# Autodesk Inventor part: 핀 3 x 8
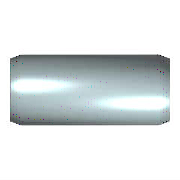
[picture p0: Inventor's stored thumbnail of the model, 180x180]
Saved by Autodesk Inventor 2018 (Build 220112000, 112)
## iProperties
IsCustomPart: 1
Created: 2012-02
Part Number: 핀 3 x 8
Material: 강철, 연강
Description: 평행 핀
Document SubType Name: Modeling
Standard: KS B 1320
Designer: mduedu
Standards Organization: KS
Language: ko-KR
Size Designation: B 3 x  8
Categories: <MemberInstance><Categories><Category DisplayName="조임쇠" InternalName="e4da775c-781d-43d5-af7c-5136215cf5a6" Mnemonic="FSTN"><Category DisplayName="핀" InternalNa
Density: 7.85 g/cm^3
Appearance: 노란색
Mass: 0.439099 g
Surface Area: 0.870195 cm^2
Volume: 0.0559361 cm^3
Author: mduedu
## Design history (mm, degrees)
sketch "스케치"
  geometry: C1 r 1.5 at (0, 0); 1 further point
  constraints: 1 centre point, 1 coincident
  dimensions: "d1" = 3 diameter of C1 (= NND)
extrude "본체" new body sketch "스케치" distance "d2" = 8 (= NLG); taper "d3" = 0 deg
chamfer "스케치2" distance "d8" = 0.5 (= PHH); stored, may be unused: angle "d9" = 15 deg (= FAWI), second distance "d12" = 0.5 (= PHH)
body "Solid1"
chamfer "모따기1" distance "d4" = 0.5 (= PHH); stored, may be unused: angle "d5" = 15 deg (= FAWI), second distance "d11" = 0.5 (= PHH)
other parameters: "NND" = 3 [user parameter; used in 1 equation term], "NLG" = 8 [user parameter; used in 1 equation term], "PHH" = 0.5 [user parameter; used in 4 equation terms], "FAWI" = 15 deg [user parameter; used in 2 equation terms], "d13" = 0, "d15" = 0, "d16" = 0, "KAH" = 0.4 [user parameter]
